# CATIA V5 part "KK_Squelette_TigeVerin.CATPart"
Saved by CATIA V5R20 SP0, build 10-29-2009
Part number: Squelette_tige_verin
Bounding box of the stored display mesh (mm): x -200 to 200, y 121.371 to 768, z -2592 to -1487.341
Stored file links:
  G:\Khaled_CFAO_2011\ST2M\ST2M_GR2\aboulegue\Khaled\CAD_thinkMOTION\KK_Squelette_TigeVerin.CATPart
  G:\Khaled_CFAO_2011\ST2M\ST2M_GR2\aboulegue\Khaled\CAD_thinkMOTION\KK_Train_Atterrissage.CATProduct
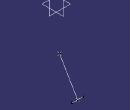
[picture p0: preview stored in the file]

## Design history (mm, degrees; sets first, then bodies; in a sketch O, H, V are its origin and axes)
Set1
  Point1 "Point.20": linked copy from another document
  Point2: linked copy from another document
  Plane1 "Plan reference": linked copy from another document
Set2 "Set squelette tige verin"
  Line1: type PtPt, FirstPoint Point1, SecondPoint Point2
  Line2: type Normal, RefPoint Point2, RefSkin Plane1, Start -200, End 200
Body1 (main body)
